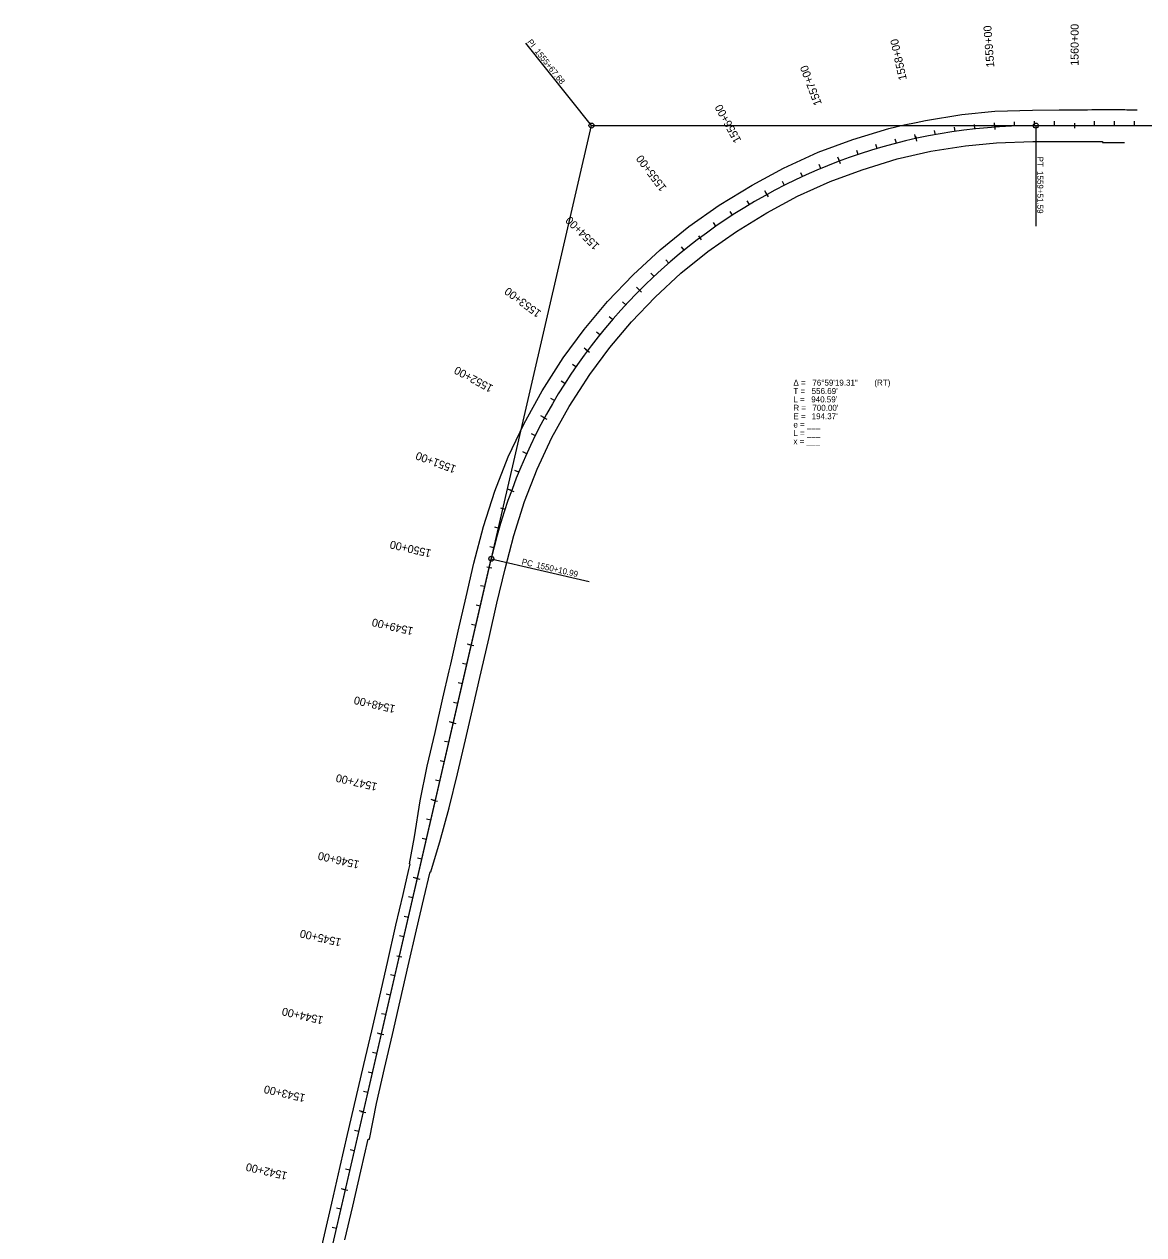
# Model space of a CAD drawing. Extents: x 21596470 to 21601942, y 8263806 to 8275912.
# Drawn here: x 21598004 to 21599406, y 8274396 to 8275912 of the extents above; entities that cross this region are included whole.
import ezdxf

# ---------------------------------------------------------------- set-up
doc = ezdxf.new("R2010")
doc.units = 0
for name, color, linetype in [('DsnShtInsideBorder', 7, 'Continuous'), ('Level 1', 7, 'Continuous'), ('Level 20', 7, 'Continuous'), ('SurTxtLeaderLine', 7, 'Continuous'), ('SurTxtSurveyInformation', 7, 'Continuous'), ('wetNoteSoil', 7, 'Continuous')]:
    doc.layers.add(name, color=color, linetype=linetype)

msp = doc.modelspace()

# ---------------------------------------------------------------- linework, layer by layer
at = {"layer": 'DsnShtInsideBorder'}
for p, q in [((21598714.2, 8275785), (21598632.1, 8275888.3)), ((21598632.1, 8275888.3), (21598632.1, 8275888.3)), ((21599270.9, 8275784.9), (21599270.9, 8275658.9)), ((21599270.9, 8275658.9), (21599270.9, 8275658.9)), ((21598588.8, 8275242.6), (21598711.5, 8275214.2)), ((21598711.5, 8275214.2), (21598711.5, 8275214.2))]:
    msp.add_line(p, q, dxfattribs=at)
for centre in [(21598714.2, 8275785), (21599270.9, 8275784.9), (21598588.8, 8275242.6)]:
    msp.add_circle(centre, 3.12, dxfattribs=at)
at = {"layer": 'Level 1'}
for p, q in [((21599219.4, 8275783), (21599219, 8275788.4)), ((21599319.3, 8275787.9), (21599319.3, 8275781.8)), ((21599120.5, 8275768.5), (21599119.3, 8275773.9)), ((21599024.7, 8275740.2), (21599022.8, 8275745.3)), ((21598933.9, 8275698.5), (21598931.3, 8275703.3)), ((21598848.1, 8275646.7), (21598851.8, 8275641.8)), ((21598774.6, 8275578.7), (21598770.7, 8275582.5)), ((21598709.4, 8275503), (21598705, 8275506.3)), ((21598655.6, 8275418.8), (21598650.8, 8275421.4)), ((21598614.3, 8275327.8), (21598609.1, 8275329.7)), ((21598583.3, 8275232.6), (21598589.3, 8275231.2)), ((21598563.7, 8275134.5), (21598558.4, 8275135.7)), ((21598541.2, 8275037.1), (21598535.9, 8275038.3)), ((21598518.7, 8274939.6), (21598513.3, 8274940.9)), ((21598496.1, 8274842.2), (21598490.8, 8274843.4)), ((21598470.6, 8274745.5), (21598476.6, 8274744.1)), ((21598451, 8274647.4), (21598445.7, 8274648.6)), ((21598428.5, 8274549.9), (21598423.2, 8274551.2)), ((21598406, 8274452.5), (21598400.6, 8274453.7))]:
    msp.add_line(p, q, dxfattribs=at)
at = {"layer": 'Level 20'}
for p, q in [((21596601.4, 8266652.3), (21598714.2, 8275785)), ((21598714.2, 8275785), (21601932.5, 8275784.2)), ((21599270.9, 8275784.9), (21601932.5, 8275784.2)), ((21596728.7, 8267202.6), (21598588.8, 8275242.6))]:
    msp.add_line(p, q, dxfattribs=at)
msp.add_arc((21599270.7, 8275084.9), 700, 89.9853, 166.974, dxfattribs=at)
msp.add_arc((21599270.7, 8275084.9), 700, 89.9853, 166.974, dxfattribs=at)
at = {"layer": 'SurTxtLeaderLine'}
msp.add_line((21599354.3, 8275765.1), (21599354.3, 8275763.8), dxfattribs=at)
for points in [[(21598512.2, 8274850.7), (21598513.2, 8274850.6), (21598514, 8274853.5), (21598524.2, 8274888), (21598535.9, 8274930.7), (21598546.4, 8274973.4), (21598556.3, 8275015.8), (21598566.5, 8275059.1), (21598574.5, 8275093.9), (21598576.2, 8275101), (21598586, 8275144), (21598595.9, 8275186.9), (21598606.2, 8275229.9), (21598616.9, 8275271.7), (21598630.2, 8275314.2), (21598646.2, 8275354.7), (21598664.8, 8275394.4), (21598686.3, 8275433.2), (21598712, 8275473.1), (21598737.4, 8275507), (21598764.3, 8275539.1), (21598794, 8275570.2), (21598826.2, 8275600), (21598860.2, 8275627.3), (21598895.9, 8275652.1), (21598933.8, 8275675.8), (21598972.2, 8275696.5), (21599013.3, 8275714.8), (21599053.1, 8275729.7), (21599097.2, 8275743.2), (21599139.5, 8275752.9), (21599182.6, 8275759.7), (21599221.6, 8275763.2), (21599266.9, 8275765), (21599300.7, 8275765.2), (21599340.7, 8275765.2), (21599354.3, 8275765.1)], [(21599354.3, 8275763.8), (21599358, 8275763.8), (21599360.3, 8275763.8), (21599382, 8275763.9)], [(21598405.4, 8274389.7), (21598415.4, 8274432), (21598425.5, 8274475.9), (21598434.6, 8274516), (21598436.4, 8274515.7), (21598445, 8274560.6), (21598455, 8274604.1), (21598465, 8274646.7), (21598474.8, 8274689.1), (21598484.7, 8274733), (21598495.1, 8274777.9), (21598504.4, 8274817.1), (21598512.2, 8274850.7)]]:
    msp.add_lwpolyline(points, dxfattribs=at)
at = {"layer": 'SurTxtSurveyInformation'}
msp.add_line((21599355.8, 8275805), (21599357.3, 8275805.1), dxfattribs=at)
for points in [[(21598487.1, 8274860.2), (21598486.2, 8274860.5), (21598492.4, 8274894.5), (21598499.7, 8274939.6), (21598508.3, 8274982.8), (21598518.3, 8275025.2), (21598528.1, 8275068.1), (21598535.9, 8275102), (21598537.9, 8275110.7), (21598547.2, 8275151.8), (21598557.4, 8275194.9), (21598567.1, 8275237), (21598579, 8275283), (21598593.1, 8275327.2), (21598610, 8275370.1), (21598629.8, 8275412), (21598652.4, 8275452.9), (21598679, 8275494.3), (21598705, 8275529.5), (21598734.4, 8275564.8), (21598766.4, 8275598.2), (21598800.2, 8275629.2), (21598836.1, 8275658.4), (21598874.1, 8275685.2), (21598915.4, 8275710.5), (21598954.7, 8275731.5), (21598998, 8275751.5), (21599041.4, 8275767.3), (21599086.8, 8275781.2), (21599106, 8275785.9), (21599121.1, 8275788.9), (21599132.6, 8275791.2), (21599178.3, 8275798.6), (21599219.5, 8275802.9), (21599266.5, 8275804.3), (21599299.9, 8275804.7), (21599335.7, 8275804.6), (21599340.8, 8275804.9), (21599355.8, 8275805)], [(21599357.3, 8275805.1), (21599361.9, 8275805.1), (21599382.2, 8275804.9), (21599384.6, 8275804.6), (21599397.9, 8275804.8)], [(21598369.7, 8274352.2), (21598379.8, 8274396.2), (21598388.9, 8274435.7), (21598399.5, 8274481.6), (21598408.8, 8274521.7), (21598419, 8274566.3), (21598429, 8274609.4), (21598439, 8274651.6), (21598449, 8274694.9), (21598458.8, 8274737.1), (21598469.4, 8274783.6), (21598478.4, 8274822), (21598485.6, 8274853.5), (21598487.1, 8274860.2)]]:
    msp.add_lwpolyline(points, dxfattribs=at)
at = {"layer": 'wetNoteSoil'}
for p, q in [((21599145, 8275773.5), (21599144, 8275778.8)), ((21599169.7, 8275777.5), (21599168.9, 8275782.9)), ((21599194.5, 8275780.7), (21599193.9, 8275786.1)), ((21599219.2, 8275786), (21599219.6, 8275779.9)), ((21599244.3, 8275784.4), (21599244.1, 8275789.8)), ((21599269.3, 8275784.8), (21599269.3, 8275790.3)), ((21599294.3, 8275784.8), (21599294.3, 8275790.3)), ((21599319.3, 8275787.9), (21599319.3, 8275781.8)), ((21599344.3, 8275784.8), (21599344.3, 8275790.3)), ((21599369.3, 8275784.8), (21599369.3, 8275790.3)), ((21599394.3, 8275784.8), (21599394.3, 8275790.3)), ((21599096.2, 8275762.7), (21599094.8, 8275768)), ((21599119.9, 8275771.5), (21599121.2, 8275765.6)), ((21599048.3, 8275748.6), (21599046.5, 8275753.7)), ((21599072.1, 8275756.1), (21599070.6, 8275761.3)), ((21599001.5, 8275731), (21598999.4, 8275736)), ((21599023.6, 8275743.1), (21599025.8, 8275737.3)), ((21598978.6, 8275721), (21598976.3, 8275725.9)), ((21598956, 8275710.1), (21598953.6, 8275715)), ((21598912.2, 8275686.1), (21598909.4, 8275690.8)), ((21598932.4, 8275701.2), (21598935.4, 8275695.8)), ((21598891, 8275672.9), (21598888, 8275677.5)), ((21598870.2, 8275658.9), (21598867.1, 8275663.4)), ((21598848.1, 8275646.7), (21598851.8, 8275641.8)), ((21598830.3, 8275628.9), (21598826.8, 8275633.1)), ((21598811.1, 8275612.8), (21598807.5, 8275616.9)), ((21598792.6, 8275596.1), (21598788.8, 8275600.1)), ((21598772.4, 8275580.8), (21598776.8, 8275576.5)), ((21598757.3, 8275560.6), (21598753.3, 8275564.4)), ((21598740.6, 8275542), (21598736.5, 8275545.6)), ((21598724.7, 8275522.8), (21598720.4, 8275526.2)), ((21598706.9, 8275504.8), (21598711.8, 8275501.2)), ((21598694.8, 8275482.7), (21598690.3, 8275485.8)), ((21598681, 8275461.9), (21598676.4, 8275464.8)), ((21598667.9, 8275440.6), (21598663.2, 8275443.4)), ((21598652.9, 8275420.3), (21598658.2, 8275417.4)), ((21598644, 8275396.6), (21598639.1, 8275399.1)), ((21598633.3, 8275374.1), (21598628.3, 8275376.3)), ((21598623.4, 8275351.1), (21598618.3, 8275353.2)), ((21598611.4, 8275328.9), (21598617.1, 8275326.8)), ((21598606, 8275304.2), (21598600.8, 8275306)), ((21598598.6, 8275280.4), (21598593.4, 8275281.9)), ((21598592, 8275256.2), (21598586.8, 8275257.6)), ((21598583.3, 8275232.6), (21598589.3, 8275231.2)), ((21598580.6, 8275207.6), (21598575.3, 8275208.8)), ((21598575, 8275183.2), (21598569.7, 8275184.4)), ((21598569.4, 8275158.8), (21598564.1, 8275160.1)), ((21598560.8, 8275135.2), (21598566.7, 8275133.8)), ((21598558.1, 8275110.1), (21598552.8, 8275111.4)), ((21598552.5, 8275085.8), (21598547.1, 8275087)), ((21598546.8, 8275061.4), (21598541.5, 8275062.7)), ((21598538.2, 8275037.8), (21598544.2, 8275036.4)), ((21598535.6, 8275012.7), (21598530.2, 8275013.9)), ((21598529.9, 8274988.3), (21598524.6, 8274989.6)), ((21598524.3, 8274964), (21598519, 8274965.2)), ((21598515.7, 8274940.3), (21598521.6, 8274938.9)), ((21598513, 8274915.3), (21598507.7, 8274916.5)), ((21598507.4, 8274890.9), (21598502.1, 8274892.2)), ((21598501.8, 8274866.6), (21598496.4, 8274867.8)), ((21598493.1, 8274842.9), (21598499.1, 8274841.5)), ((21598490.5, 8274817.9), (21598485.2, 8274819.1)), ((21598484.9, 8274793.5), (21598479.5, 8274794.7)), ((21598479.2, 8274769.1), (21598473.9, 8274770.4)), ((21598470.6, 8274745.5), (21598476.6, 8274744.1)), ((21598467.9, 8274720.4), (21598462.6, 8274721.7)), ((21598462.3, 8274696.1), (21598457, 8274697.3)), ((21598456.7, 8274671.7), (21598451.4, 8274672.9)), ((21598448.1, 8274648), (21598454, 8274646.7)), ((21598445.4, 8274623), (21598440.1, 8274624.2)), ((21598439.8, 8274598.6), (21598434.5, 8274599.9)), ((21598434.1, 8274574.3), (21598428.8, 8274575.5)), ((21598425.5, 8274550.6), (21598431.5, 8274549.2)), ((21598422.9, 8274525.6), (21598417.5, 8274526.8)), ((21598417.2, 8274501.2), (21598411.9, 8274502.4)), ((21598411.6, 8274476.9), (21598406.3, 8274478.1)), ((21598403, 8274453.2), (21598408.9, 8274451.8)), ((21598400.3, 8274428.1), (21598395, 8274429.4)), ((21598394.7, 8274403.8), (21598389.4, 8274405))]:
    msp.add_line(p, q, dxfattribs=at)

# ---------------------------------------------------------------- texts
at = {"layer": 'DsnShtInsideBorder'}
for s, rotation, p in [('PI ', 308.4797, (21598633.4, 8275889.4)), ('1555+67.68', 308.4797, (21598642.7, 8275877.6)), ('PT', 269.9853, (21599272.6, 8275746.1)), ('1559+51.59', 269.9853, (21599272.6, 8275728)), ('PC', 346.974, (21598626.3, 8275235.6)), ('1550+10.99', 346.974, (21598644.5, 8275231.4))]:
    msp.add_text(s, height=7.5, rotation=rotation, dxfattribs=at).set_placement(p)
for s, p in [('Δ = ', (21598967.2, 8275459.3)), ('76°59\'19.31"', (21598990.9, 8275459.3)), (' (RT)', (21599065.8, 8275459.3)), ('T = ', (21598967.2, 8275448.8)), ('L = ', (21598967.2, 8275438.3)), ("940.59'", (21598989.5, 8275438.3)), ("556.69'", (21598990, 8275448.8)), ('R = ', (21598967.2, 8275427.8)), ("700.00'", (21598990.9, 8275427.8)), ('E = ', (21598967.2, 8275417.3)), ("194.37'", (21598990, 8275417.3)), ('e = ___ ', (21598967.2, 8275406.8)), ('L = ___', (21598967.2, 8275396.3)), ('x = ___', (21598967.2, 8275385.8))]:
    msp.add_text(s, height=7.5, dxfattribs=at).set_placement(p)
at = {"layer": 'Level 1'}
for s, rotation, p in [('1560+00', 89.9853, (21599324.4, 8275859.8)), ('1555+00', 126.9482, (21598808.9, 8275707.2)), ('1550+00', 166.974, (21598514.3, 8275253.7)), ('1545+00', 166.974, (21598401.6, 8274766.6))]:
    msp.add_text(s, height=10.02, rotation=rotation, dxfattribs=at).set_placement(p)
at = {"layer": 'wetNoteSoil'}
for s, rotation, p in [('1559+00', 94.2077, (21599218.9, 8275858.1)), ('1560+00', 89.9853, (21599324.4, 8275859.8)), ('1558+00', 102.3928, (21599109.3, 8275842.9)), ('1557+00', 110.5779, (21599003, 8275812.2)), ('1556+00', 118.763, (21598902.2, 8275766.6)), ('1555+00', 126.9482, (21598808.9, 8275707.2)), ('1554+00', 135.1333, (21598725, 8275635.1)), ('1553+00', 143.3184, (21598652.2, 8275551.8)), ('1552+00', 151.5035, (21598592, 8275459)), ('1551+00', 159.6886, (21598545.7, 8275358.6)), ('1550+00', 166.974, (21598514.3, 8275253.7)), ('1549+00', 166.974, (21598491.8, 8275156.3)), ('1548+00', 166.974, (21598469.3, 8275058.8)), ('1547+00', 166.974, (21598446.7, 8274961.4)), ('1546+00', 166.974, (21598424.2, 8274864)), ('1545+00', 166.974, (21598401.6, 8274766.6)), ('1544+00', 166.974, (21598379.1, 8274669.1)), ('1543+00', 166.974, (21598356.6, 8274571.7)), ('1542+00', 166.974, (21598334, 8274474.3))]:
    msp.add_text(s, height=10.02, rotation=rotation, dxfattribs=at).set_placement(p)

doc.saveas('drawing.dxf')
